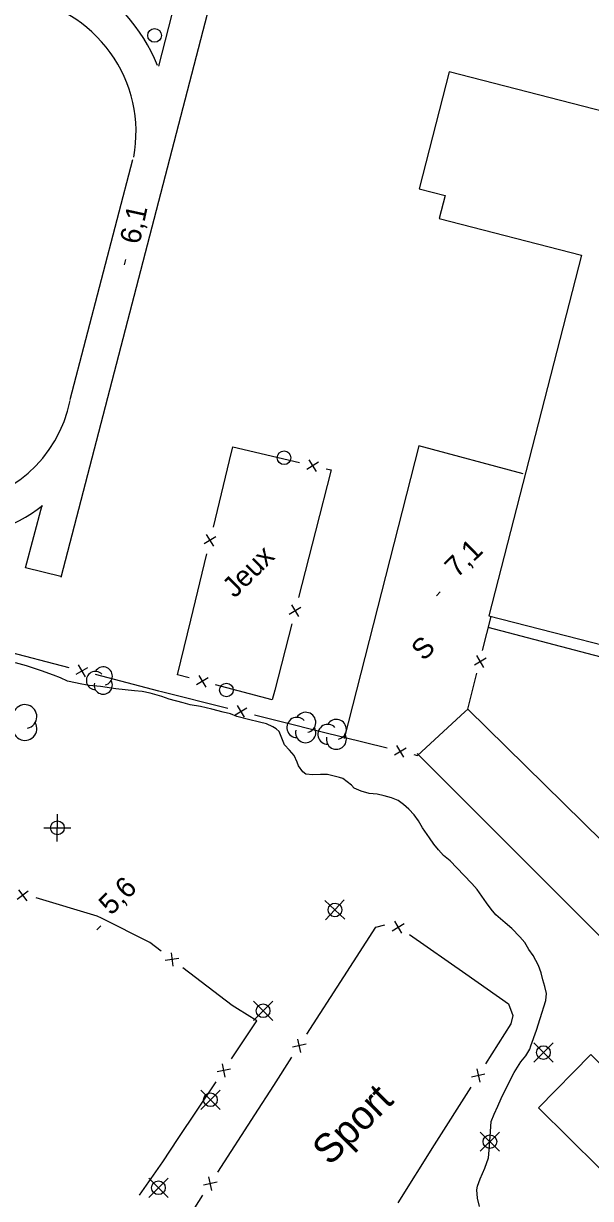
# Model space of a CAD drawing. Extents: x 381879 to 384696, y 5564785 to 5567594.
# Drawn here: x 382841.1 to 382924, y 5565288.9 to 5565460.7 of the extents above; entities that cross this region are included whole.
import ezdxf

# ---------------------------------------------------------------- set-up
doc = ezdxf.new("R2010")
doc.units = 0
for name, color, linetype in [('Niveau 19', 7, 'Continuous'), ('Niveau 2', 7, 'Continuous'), ('Niveau 22', 7, 'Continuous'), ('Niveau 3', 7, 'Continuous'), ('Niveau 31', 7, 'Continuous'), ('Niveau 36', 7, 'Continuous'), ('Niveau 37', 7, 'Continuous'), ('Niveau 44', 7, 'Continuous'), ('Niveau 52', 7, 'Continuous'), ('Niveau 56', 7, 'Continuous')]:
    doc.layers.add(name, color=color, linetype=linetype)

msp = doc.modelspace()

# ---------------------------------------------------------------- linework, layer by layer
at = {"layer": 'Niveau 19'}
for points in [[(382936.92, 5565330.06), (382906.02, 5565360.46)], [(382898.62, 5565353.97), (382929.58, 5565323)]]:
    msp.add_lwpolyline(points, dxfattribs=at)
at = {"layer": 'Niveau 2'}
for points in [[(382868.63, 5565360.44), (382867, 5565360.82), (382865.45, 5565361.09), (382864.46, 5565361.38), (382862.4, 5565361.92), (382861.35, 5565362.27), (382859.64, 5565362.77), (382858.46, 5565363.01), (382857.35, 5565363.12), (382854.6, 5565363.43), (382852.36, 5565363.74), (382850.71, 5565363.89), (382849.66, 5565364.07), (382847.54, 5565364.53), (382846.54, 5565365.03), (382845.51, 5565365.42), (382843.74, 5565366.04), (382841.56, 5565366.76), (382839.93, 5565367.22)], [(382907.76, 5565287.71), (382907.45, 5565288.93), (382907.33, 5565290.15), (382907.45, 5565290.71), (382907.84, 5565291.79), (382908.5, 5565293.32), (382909.07, 5565294.83), (382909.12, 5565295.38), (382909.28, 5565297.95), (382909.46, 5565300.15), (382909.87, 5565301.24), (382910.42, 5565302.38), (382910.9, 5565303.54), (382911.45, 5565304.65), (382912.8, 5565307.33), (382913.77, 5565308.9), (382914.52, 5565309.76), (382915.08, 5565310.73), (382915.24, 5565311.24), (382916.07, 5565313.51), (382916.62, 5565315.23), (382917.41, 5565317.85), (382917.51, 5565318.86), (382917.3, 5565319.87), (382916.98, 5565320.86), (382916.75, 5565321.91), (382916.37, 5565322.95), (382915.57, 5565324.45), (382914.96, 5565325.32), (382914.35, 5565326.32), (382913.64, 5565327.14), (382912.45, 5565328.39), (382911.49, 5565329.18), (382910.13, 5565330.39), (382909.43, 5565331.2), (382908.76, 5565332.11), (382907.38, 5565334.07), (382906.63, 5565334.93), (382905.44, 5565336.17), (382903.47, 5565338.27), (382902.48, 5565339.06), (382901.73, 5565339.85), (382901.05, 5565340.68), (382900.42, 5565341.64), (382899.4, 5565343.08), (382898.81, 5565344.11), (382898.19, 5565345), (382897.43, 5565345.8), (382896.66, 5565346.49), (382895.84, 5565347.09), (382894.86, 5565347.48), (382893.81, 5565347.79), (382892.79, 5565348.01), (382891.64, 5565348.13), (382890.47, 5565348.45), (382889.45, 5565348.9), (382889.05, 5565349.33), (382887.79, 5565350.32), (382887.27, 5565350.47), (382885.55, 5565350.9), (382884.5, 5565350.91), (382883.41, 5565350.83), (382882.38, 5565350.93), (382881.95, 5565351.3), (382881.29, 5565352.13), (382881.12, 5565352.67), (382880.67, 5565353.65), (382879.99, 5565354.44), (382879.24, 5565355.21), (382879.05, 5565355.73), (382878.45, 5565357.18), (382878.05, 5565357.54), (382877.56, 5565357.84), (382876.61, 5565358.27), (382875.62, 5565358.54), (382873.97, 5565358.93), (382872.29, 5565359.39), (382871.34, 5565359.77), (382870.29, 5565360), (382868.63, 5565360.44)]]:
    msp.add_lwpolyline(points, dxfattribs=at)
at = {"layer": 'Niveau 22'}
msp.add_lwpolyline([(382908.95, 5565372.45), (382943.82, 5565363.28), (382962.06, 5565349.67)], dxfattribs=at)
at = {"layer": 'Niveau 3'}
for p, q in [((382855.89, 5565425.42), (382856.07, 5565426.2)), ((382901.44, 5565377), (382902.01, 5565377.57)), ((382851.84, 5565328.18), (382852.41, 5565328.75))]:
    msp.add_line(p, q, dxfattribs=at)
at = {"layer": 'Niveau 31'}
for points in [[(382958.53, 5565443.51), (382938.53, 5565448.64), (382937.54, 5565444.79), (382903.33, 5565453.59), (382898.94, 5565436.52), (382902.71, 5565435.55), (382901.84, 5565432.17), (382922.64, 5565426.82), (382909.08, 5565374.08), (382937.21, 5565366.85), (382943.07, 5565389.63), (382940.9, 5565390.19), (382948.64, 5565420.18), (382952.3, 5565419.24)], [(382929.65, 5565289.01), (382916.35, 5565302.18), (382924.02, 5565309.93), (382929.46, 5565304.54), (382930.42, 5565305.51), (382932.93, 5565303.04), (382932.06, 5565302.16), (382939.03, 5565295.26), (382935.9, 5565292.11), (382934.27, 5565293.7)]]:
    msp.add_lwpolyline(points, close=True, dxfattribs=at)
at = {"layer": 'Niveau 36'}
for p, q in [((382846.05, 5565341.09), (382846.07, 5565345.08)), ((382844.07, 5565343.09), (382848.05, 5565343.08)), ((382885.25, 5565329.64), (382887.97, 5565332.55)), ((382885.15, 5565332.45), (382888.06, 5565329.73)), ((382877.54, 5565317.75), (382874.72, 5565314.93)), ((382877.54, 5565314.93), (382874.72, 5565317.75)), ((382918.5, 5565311.64), (382915.68, 5565308.82)), ((382918.5, 5565308.82), (382915.68, 5565311.64)), ((382869.84, 5565304.74), (382867.02, 5565301.92)), ((382869.84, 5565301.92), (382867.02, 5565304.74)), ((382910.68, 5565298.62), (382907.86, 5565295.8)), ((382910.68, 5565295.8), (382907.86, 5565298.62)), ((382862.26, 5565291.88), (382859.44, 5565289.06)), ((382862.26, 5565289.06), (382859.44, 5565291.88))]:
    msp.add_line(p, q, dxfattribs=at)
for centre in [(382860.26, 5565458.94), (382879.18, 5565397.19), (382870.77, 5565363.24), (382846.07, 5565343.09), (382876.12, 5565316.34), (382917.08, 5565310.23), (382868.42, 5565303.33), (382909.26, 5565297.21), (382860.84, 5565290.47)]:
    msp.add_circle(centre, 1, dxfattribs=at)
msp.add_ellipse((382886.62, 5565331.09), major_axis=(-0.048, -0.999), ratio=0.999982, dxfattribs=at)
at = {"layer": 'Niveau 37'}
for p, q in [((382882.53, 5565395.52), (382884.24, 5565396.58)), ((382883.91, 5565395.2), (382882.86, 5565396.9)), ((382868.91, 5565384.26), (382867.87, 5565385.97)), ((382869.24, 5565385.64), (382867.53, 5565384.59)), ((382880.29, 5565375.7), (382881.31, 5565373.98)), ((382879.94, 5565374.33), (382881.66, 5565375.35)), ((382850.17, 5565365.18), (382849.16, 5565366.91)), ((382908.71, 5565367.91), (382906.99, 5565366.88)), ((382908.36, 5565366.54), (382907.34, 5565368.26)), ((382848.8, 5565365.54), (382850.53, 5565366.55)), ((382866.75, 5565365.35), (382867.76, 5565363.63)), ((382868.12, 5565365), (382866.39, 5565363.98)), ((382872.06, 5565359.59), (382873.77, 5565360.62)), ((382873.43, 5565359.25), (382872.4, 5565360.96)), ((382896.7, 5565353.43), (382895.67, 5565355.14)), ((382895.33, 5565353.77), (382897.05, 5565354.8)), ((382841.81, 5565333.81), (382840.2, 5565332.61)), ((382840.41, 5565334.02), (382841.6, 5565332.41)), ((382895, 5565328.05), (382896.72, 5565329.08)), ((382896.38, 5565327.71), (382895.35, 5565329.43)), ((382863.81, 5565323.98), (382861.83, 5565323.71)), ((382862.69, 5565324.84), (382862.95, 5565322.85)), ((382881.63, 5565310.26), (382881.21, 5565312.21)), ((382882.4, 5565311.45), (382880.44, 5565311.02)), ((382870.58, 5565306.65), (382870.18, 5565308.61)), ((382871.36, 5565307.83), (382869.4, 5565307.44)), ((382906.57, 5565306.67), (382908.53, 5565307.11)), ((382907.33, 5565307.86), (382907.77, 5565305.91)), ((382869.39, 5565291.28), (382867.43, 5565290.86)), ((382868.62, 5565290.09), (382868.2, 5565292.05))]:
    msp.add_line(p, q, dxfattribs=at)
for points in [[(382871.21, 5565396.78), (382871.7, 5565398.78)], [(382871.7, 5565398.78), (382881.44, 5565396.5)], [(382868.86, 5565387.06), (382871.21, 5565396.78)], [(382885.33, 5565395.59), (382886.07, 5565395.42), (382883.78, 5565386.47)], [(382883.78, 5565386.47), (382881.3, 5565376.78)], [(382865.56, 5565373.45), (382867.92, 5565383.17)], [(382908.2, 5565369.02), (382909.44, 5565373.99)], [(382865.32, 5565365), (382863.62, 5565365.44), (382865.56, 5565373.45)], [(382880.31, 5565372.9), (382877.83, 5565363.22)], [(382838.05, 5565369.08), (382847.73, 5565366.55)], [(382851.6, 5565365.54), (382860.83, 5565363.12), (382861.27, 5565363.01)], [(382905.6, 5565360.07), (382906.02, 5565360.46), (382907.35, 5565365.72)], [(382877.83, 5565363.22), (382877.47, 5565361.82), (382869.19, 5565363.98)], [(382861.27, 5565363.01), (382870.97, 5565360.59)], [(382898.13, 5565353.8), (382898.69, 5565353.66), (382905.6, 5565360.07)], [(382874.85, 5565359.62), (382878.94, 5565358.6), (382878.94, 5565358.59), (382878.95, 5565358.59), (382884.55, 5565357.19)], [(382884.55, 5565357.19), (382894.25, 5565354.77)], [(382852.51, 5565329.89), (382851.89, 5565330.2), (382842.97, 5565332.87)], [(382861.23, 5565325.06), (382859.57, 5565326.33), (382852.51, 5565329.89)], [(382887.92, 5565321.32), (382892.61, 5565328.59), (382893.92, 5565328.91)], [(382897.53, 5565327.48), (382905.72, 5565321.74)], [(382872.4, 5565316.63), (382871.61, 5565317.12), (382864.41, 5565322.63)], [(382882.5, 5565312.92), (382887.92, 5565321.32)], [(382905.72, 5565321.74), (382911.98, 5565317.36)], [(382911.98, 5565317.36), (382912.61, 5565315.65), (382912.32, 5565314.44), (382908.62, 5565308.58)], [(382871.49, 5565309.3), (382875.2, 5565314.87), (382872.4, 5565316.63)], [(382874.91, 5565301.15), (382877.68, 5565305.44), (382880.33, 5565309.56)], [(382863.73, 5565297.65), (382869.27, 5565305.97)], [(382906.48, 5565305.2), (382901.14, 5565296.74)], [(382869.5, 5565292.75), (382874.91, 5565301.15)], [(382858.07, 5565289.4), (382861.46, 5565294.24), (382863.73, 5565297.65)], [(382901.14, 5565296.74), (382895.8, 5565288.29)], [(382869.19, 5565281.45), (382866.35, 5565283.38), (382865.57, 5565285.52), (382866.15, 5565287.56), (382867.33, 5565289.39)]]:
    msp.add_lwpolyline(points, dxfattribs=at)
at = {"layer": 'Niveau 44'}
for centre, radius, start, end in [((382851.63, 5565364.63), 1.33, 44.1153, 269.8039), ((382852.77, 5565365.29), 1.33, 282.2692, 149.7262), ((382852.77, 5565363.96), 1.33, 166.9368, 29.6212), ((382841.33, 5565359.36), 1.74, 282.2692, 149.7262), ((382882.34, 5565358.5), 1.48, 282.2692, 149.7262), ((382841.33, 5565357.62), 1.74, 166.9368, 29.6212), ((382881.07, 5565357.76), 1.48, 44.1153, 269.8039), ((382886.83, 5565357.49), 1.46, 282.2692, 149.7262), ((382882.34, 5565357.02), 1.48, 166.9368, 29.6212), ((382885.58, 5565356.76), 1.46, 44.1153, 269.8039), ((382886.83, 5565356.03), 1.46, 166.9368, 29.6212)]:
    msp.add_arc(centre, radius, start, end, dxfattribs=at)
at = {"layer": 'Niveau 52'}
msp.add_lwpolyline([(382914.14, 5565394.86), (382898.87, 5565398.92), (382887.99, 5565356.17)], dxfattribs=at)
at = {"layer": 'Niveau 56'}
for points in [[(382860.87, 5565454.45), (382869.61, 5565488.51)], [(382874.45, 5565487.04), (382846.55, 5565379.67)], [(382847.92, 5565405.69), (382857.07, 5565440.78)], [(382841.43, 5565381.09), (382843.85, 5565390.27)], [(382846.59, 5565379.84), (382841.43, 5565381.09)]]:
    msp.add_lwpolyline(points, dxfattribs=at)
for centre, radius, start, end in [((382837.91, 5565445.49), 24.51, 21.6082, 102.9683), ((382837.62, 5565444.76), 19.94, 349.5513, 82.0559), ((382829.2, 5565409.36), 19.13, 273.6601, 348.5681), ((382828.62, 5565409.89), 24.92, 235.6332, 307.8394)]:
    msp.add_arc(centre, radius, start, end, dxfattribs=at)

# ---------------------------------------------------------------- texts
at = {"layer": 'Niveau 3'}
for s, rotation, p in [('6,1  ', 77.7252, (382858.07, 5565428.28)), ('7,1  ', 44.7717, (382904.47, 5565379.51)), ('5,6  ', 44.7717, (382853.91, 5565330.18))]:
    msp.add_text(s, height=3, rotation=rotation, dxfattribs=at).set_placement(p)
at = {"layer": 'Niveau 52'}
msp.add_text('S', height=3, rotation=44.7717, dxfattribs=at).set_placement((382899.58, 5565367.37))
at = {"layer": 'Niveau 56'}
for s, height, p in [('Jeux', 3, (382871.98, 5565376.57)), ('Sport', 4.2, (382885.86, 5565293.57))]:
    msp.add_text(s, height=height, rotation=44.7717, dxfattribs=at).set_placement(p)

doc.saveas('drawing.dxf')
